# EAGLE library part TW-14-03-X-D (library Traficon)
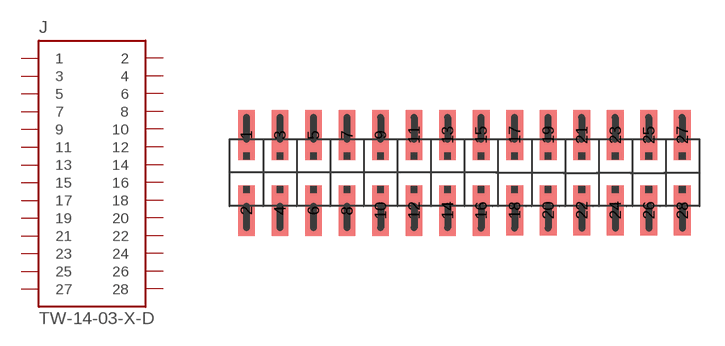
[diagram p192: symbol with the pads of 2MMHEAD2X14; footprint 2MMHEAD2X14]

Designator prefix J

## TW-14-03-X-D  [2MMHEAD2X14]
1  1  pas
2  2  pas
3  3  pas
4  4  pas
5  5  pas
6  6  pas
7  7  pas
8  8  pas
9  9  pas
10  10  pas
11  11  pas
12  12  pas
13  13  pas
14  14  pas
15  15  pas
16  16  pas
17  17
18  18
19  19
20  20
21  21
22  22
23  23
24  24
25  25
26  26
27  27
28  28

## Footprint 2MMHEAD2X14 (pad centres in mm)
smd 1 x 3: 1 -12.988,2.305; 2 -12.988,-2.215; 3 -10.988,2.305; 4 -10.988,-2.215; 5 -8.988,2.305; 6 -8.988,-2.215; 7 -6.988,2.305; 8 -6.988,-2.215; 9 -4.988,2.305; 10 -4.988,-2.215; 11 -2.988,2.305; 12 -2.988,-2.215; 13 -0.988,2.305; 14 -0.988,-2.215; 15 1.012,2.305; 16 1.012,-2.215; 17 3.012,2.305; 18 3.012,-2.195; 19 5.012,2.305; 20 5.012,-2.195; 21 7.018,2.302; 22 7.018,-2.198; 23 9.018,2.302; 24 9.018,-2.198; 25 11.018,2.302; 26 11.018,-2.198; 27 13.018,2.302; 28 13.018,-2.198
